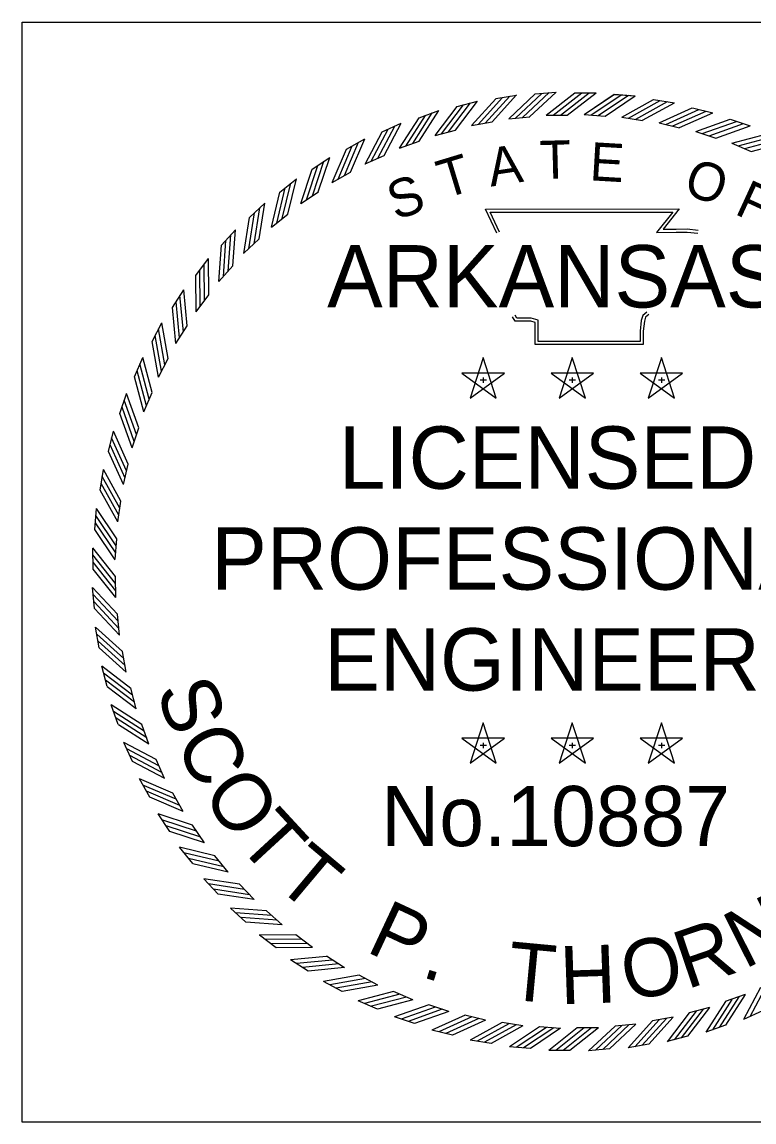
# Model space of a CAD drawing. Extents: x 0 to 1228740, y 0 to 152440.
# Drawn here: x 34.774 to 36.607, y 17.436 to 20.192 of the extents above; entities that cross this region are included whole.
import ezdxf

# ---------------------------------------------------------------- set-up
doc = ezdxf.new("R2010")
doc.units = 0
doc.layers.add('R_Sheet Text', color=7, linetype='Continuous')

msp = doc.modelspace()

# ---------------------------------------------------------------- linework, layer by layer
at = {"layer": 'R_Sheet Text'}
for p, q in [((36.0588, 20.0118), (36.1112, 20.0166)), ((36.1585, 20.0147), (36.2111, 20.0147)), ((35.8631, 19.9801), (35.914, 19.9935)), ((35.9603, 20), (36.0121, 20.0091)), ((36.257, 20.0107), (36.3095, 20.0069)), ((36.2571, 20.0108), (36.3096, 20.0069)), ((36.3554, 19.998), (36.4074, 19.9898)), ((35.7679, 19.9523), (35.8175, 19.9699)), ((36.0866, 19.9587), (36.1394, 19.9587)), ((36.1812, 19.9602), (36.2339, 19.9563)), ((36.1813, 19.9602), (36.2339, 19.9563)), ((36.4524, 19.9771), (36.5035, 19.9647)), ((35.6753, 19.9167), (35.7233, 19.9383)), ((35.8993, 19.9324), (35.9513, 19.9415)), ((35.9924, 19.9494), (36.045, 19.9542)), ((36.2757, 19.9538), (36.3279, 19.9456)), ((36.3694, 19.9397), (36.4206, 19.9272)), ((36.5473, 19.9483), (36.5972, 19.9317)), ((35.8079, 19.9077), (35.8589, 19.9211)), ((36.4615, 19.9179), (36.5115, 19.9012)), ((35.586, 19.8736), (35.632, 19.8991)), ((35.7189, 19.8756), (35.7686, 19.8932)), ((36.5515, 19.8886), (36.6, 19.8678)), ((35.5005, 19.8233), (35.5443, 19.8525)), ((35.6328, 19.8362), (35.6809, 19.8578)), ((35.4195, 19.766), (35.4607, 19.7987)), ((35.5503, 19.7899), (35.5964, 19.8154)), ((35.4718, 19.7368), (35.5157, 19.7661)), ((35.3435, 19.7023), (35.3819, 19.7383)), ((35.398, 19.6775), (35.4394, 19.7103)), ((35.273, 19.6325), (35.3083, 19.6716)), ((35.3294, 19.6124), (35.3679, 19.6484)), ((35.2085, 19.5572), (35.2404, 19.599)), ((35.2664, 19.5417), (35.3017, 19.5809)), ((35.1504, 19.4767), (35.1788, 19.5211)), ((35.2094, 19.4661), (35.2414, 19.508)), ((35.0992, 19.3918), (35.1238, 19.4383)), ((35.1589, 19.3861), (35.1873, 19.4305)), ((35.0552, 19.3029), (35.0759, 19.3513)), ((35.9285, 19.3507), (35.8956, 19.2497)), ((35.9613, 19.2498), (35.9286, 19.3509)), ((36.1517, 19.3507), (36.1188, 19.2497)), ((36.1845, 19.2498), (36.1518, 19.3509)), ((36.3749, 19.3507), (36.342, 19.2497)), ((36.4077, 19.2498), (36.375, 19.3509)), ((35.1151, 19.3021), (35.1398, 19.3487)), ((35.9816, 19.3122), (35.8753, 19.3123)), ((35.8754, 19.3122), (35.9613, 19.2497)), ((35.8957, 19.2498), (35.9817, 19.3122)), ((35.9286, 19.3009), (35.9286, 19.2876)), ((36.2048, 19.3122), (36.0986, 19.3123)), ((36.0986, 19.3122), (36.1845, 19.2497)), ((36.1189, 19.2498), (36.2049, 19.3122)), ((36.1518, 19.3009), (36.1518, 19.2876)), ((36.428, 19.3122), (36.3218, 19.3123)), ((36.3218, 19.3122), (36.4077, 19.2497)), ((36.3421, 19.2498), (36.4281, 19.3122)), ((36.375, 19.3009), (36.375, 19.2876)), ((35.9209, 19.2952), (35.9367, 19.2952)), ((36.1441, 19.2952), (36.1599, 19.2952)), ((36.3674, 19.2952), (36.3831, 19.2952)), ((35.0187, 19.2107), (35.0353, 19.2606)), ((35.0784, 19.2149), (35.0992, 19.2633)), ((34.9899, 19.1157), (35.0023, 19.1669)), ((35.0491, 19.1248), (35.0658, 19.1749)), ((35.0273, 19.0327), (35.0398, 19.084)), ((34.969, 19.0188), (34.9772, 19.0708)), ((34.9563, 18.9204), (34.9601, 18.9729)), ((35.0132, 18.9391), (35.0214, 18.9912)), ((35.0068, 18.8447), (35.0107, 18.8973)), ((34.9517, 18.8213), (34.9512, 18.8739)), ((35.0083, 18.75), (35.0078, 18.8028)), ((34.9552, 18.7222), (34.9504, 18.7746)), ((35.0176, 18.6558), (35.0128, 18.7083)), ((34.967, 18.6237), (34.9579, 18.6755)), ((35.0346, 18.5627), (35.0255, 18.6146)), ((34.9869, 18.5265), (34.9735, 18.5774)), ((35.0593, 18.4713), (35.0459, 18.5223)), ((35.0147, 18.4313), (34.9971, 18.4809)), ((35.0914, 18.3823), (35.0738, 18.432)), ((35.9285, 18.4355), (35.8956, 18.3345)), ((35.9613, 18.3346), (35.9286, 18.4357)), ((36.1517, 18.4355), (36.1188, 18.3345)), ((36.1845, 18.3346), (36.1518, 18.4357)), ((36.3749, 18.4355), (36.342, 18.3345)), ((36.4077, 18.3346), (36.375, 18.4357)), ((35.0503, 18.3387), (35.0287, 18.3867)), ((35.9816, 18.397), (35.8753, 18.3971)), ((35.8754, 18.397), (35.9613, 18.3345)), ((35.8957, 18.3346), (35.9817, 18.397)), ((36.2048, 18.397), (36.0986, 18.3971)), ((36.0986, 18.397), (36.1845, 18.3345)), ((36.1189, 18.3346), (36.2049, 18.397)), ((36.428, 18.397), (36.3218, 18.3971)), ((36.3218, 18.397), (36.4077, 18.3345)), ((36.3421, 18.3346), (36.4281, 18.397)), ((35.9209, 18.38), (35.9367, 18.38)), ((35.9286, 18.3857), (35.9286, 18.3724)), ((36.1441, 18.38), (36.1599, 18.38)), ((36.1518, 18.3857), (36.1518, 18.3724)), ((36.3674, 18.38), (36.3831, 18.38)), ((36.375, 18.3857), (36.375, 18.3724)), ((35.1308, 18.2962), (35.1092, 18.3443)), ((35.0934, 18.2494), (35.0679, 18.2954)), ((35.1771, 18.2136), (35.1516, 18.2598)), ((35.1437, 18.1639), (35.1145, 18.2077)), ((35.2302, 18.1352), (35.2009, 18.1791)), ((35.201, 18.0829), (35.1683, 18.1241)), ((35.2895, 18.0614), (35.2567, 18.1027)), ((35.2647, 18.0068), (35.2287, 18.0452)), ((35.3546, 17.9928), (35.3186, 18.0312)), ((35.3345, 17.9364), (35.2954, 17.9716)), ((35.4253, 17.9297), (35.3862, 17.9651)), ((35.4098, 17.8719), (35.368, 17.9038)), ((35.5009, 17.8728), (35.459, 17.9048)), ((35.4903, 17.8138), (35.4459, 17.8422)), ((35.5809, 17.8222), (35.5365, 17.8507)), ((35.5752, 17.7626), (35.5287, 17.7872)), ((35.6649, 17.7785), (35.6183, 17.8032)), ((35.7522, 17.7418), (35.7037, 17.7626)), ((36.5847, 17.7548), (36.535, 17.7372)), ((35.6641, 17.7186), (35.6157, 17.7393)), ((35.8422, 17.7125), (35.7921, 17.7291)), ((35.7563, 17.682), (35.7064, 17.6987)), ((35.9343, 17.6907), (35.883, 17.7032)), ((36.4043, 17.698), (36.3524, 17.6888)), ((36.4957, 17.7227), (36.4447, 17.7093)), ((36.6283, 17.7137), (36.5803, 17.6921)), ((36.0279, 17.6766), (35.9758, 17.6848)), ((36.1223, 17.6702), (36.0697, 17.6741)), ((36.217, 17.6717), (36.1642, 17.6712)), ((36.3112, 17.681), (36.2587, 17.6761)), ((36.5357, 17.6781), (36.4861, 17.6605)), ((35.8513, 17.6533), (35.8001, 17.6657)), ((36.4405, 17.6503), (36.3896, 17.6369)), ((35.9482, 17.6324), (35.8963, 17.6406)), ((36.0466, 17.6196), (35.9941, 17.6235)), ((36.1457, 17.615), (36.0931, 17.6145)), ((36.2448, 17.6186), (36.1924, 17.6138)), ((36.3433, 17.6304), (36.2915, 17.6213))]:
    msp.add_line(p, q, dxfattribs=at)
msp.add_lwpolyline([(34.7735, 20.192), (37.53, 20.192), (37.53, 17.4355), (34.7735, 17.4355)], close=True, dxfattribs=at)
for points in [[(36.0093, 19.9508), (36.0756, 20.0131)], [(36.0274, 19.9528), (36.0938, 20.0152)], [(36.0449, 19.9543), (36.1113, 20.0166)], [(36.0866, 19.9586), (36.1584, 20.0146)], [(36.1035, 19.9585), (36.1753, 20.0145)], [(36.1218, 19.9589), (36.1936, 20.0149)], [(36.1393, 19.9587), (36.2111, 20.0147)], [(35.8419, 19.9168), (35.8971, 19.9893)], [(35.8589, 19.9211), (35.9141, 19.9936)], [(35.8993, 19.9323), (35.9602, 19.9999)], [(35.916, 19.9351), (35.977, 20.0027)], [(35.9339, 19.9387), (35.9949, 20.0063)], [(35.9512, 19.9416), (36.0122, 20.0092)], [(35.9924, 19.9494), (36.0587, 20.0117)], [(36.1812, 19.9601), (36.257, 20.0108)], [(36.1812, 19.9601), (36.2569, 20.0107)], [(36.1981, 19.9587), (36.2739, 20.0094)], [(36.1981, 19.9587), (36.2738, 20.0093)], [(36.2163, 19.9578), (36.2922, 20.0084)], [(36.2164, 19.9578), (36.2921, 20.0084)], [(36.2338, 19.9563), (36.3096, 20.007)], [(36.2338, 19.9563), (36.3096, 20.0069)], [(36.2757, 19.9538), (36.3553, 19.9979)], [(36.2924, 19.951), (36.372, 19.9951)], [(36.3105, 19.9486), (36.3901, 19.9927)], [(36.3278, 19.9457), (36.4074, 19.9898)], [(35.7349, 19.881), (35.7839, 19.9577)], [(35.752, 19.8875), (35.801, 19.9642)], [(35.7685, 19.8932), (35.8176, 19.9699)], [(35.8079, 19.9076), (35.8631, 19.9801)], [(35.8243, 19.9118), (35.8795, 19.9842)], [(36.3693, 19.9397), (36.4523, 19.9771)], [(36.3857, 19.9355), (36.4687, 19.9729)], [(36.4036, 19.9316), (36.4866, 19.969)], [(36.4205, 19.9273), (36.5036, 19.9647)], [(35.6648, 19.8508), (35.7073, 19.9313)], [(35.6808, 19.8578), (35.7233, 19.9384)], [(35.7188, 19.8755), (35.7679, 19.9522)], [(36.4614, 19.9179), (36.5472, 19.9483)], [(36.4774, 19.9124), (36.5632, 19.9428)], [(36.4949, 19.907), (36.5807, 19.9374)], [(36.5115, 19.9013), (36.5973, 19.9317)], [(35.6328, 19.8361), (35.6753, 19.9166)], [(35.6483, 19.8429), (35.6908, 19.9235)], [(36.5514, 19.8885), (36.6394, 19.9118)], [(36.5669, 19.8817), (36.6549, 19.905)], [(35.5651, 19.7978), (35.6008, 19.8816)], [(35.5809, 19.807), (35.6166, 19.8908)], [(35.5963, 19.8154), (35.6321, 19.8991)], [(36.5839, 19.8749), (36.6719, 19.8982)], [(36.5999, 19.8679), (36.688, 19.8911)], [(35.5156, 19.7661), (35.5443, 19.8525)], [(35.5502, 19.7898), (35.5859, 19.8735)], [(35.4718, 19.7368), (35.5005, 19.8232)], [(35.486, 19.746), (35.5147, 19.8325)], [(35.501, 19.7565), (35.5296, 19.8429)], [(35.4393, 19.7103), (35.4607, 19.7988)], [(35.398, 19.6775), (35.4195, 19.766)], [(35.4114, 19.6879), (35.4328, 19.7764)], [(35.4254, 19.6995), (35.4469, 19.788)], [(35.3678, 19.6484), (35.3819, 19.7384)], [(35.3418, 19.6237), (35.3559, 19.7137)], [(35.3549, 19.6365), (35.369, 19.7265)], [(35.9624, 19.6625), (35.9343, 19.7232), (36.4197, 19.7235), (36.3791, 19.6726), (36.4121, 19.673), (36.4396, 19.6734), (36.4672, 19.6704)], [(35.9694, 19.6657), (35.9464, 19.7156), (36.4037, 19.7158), (36.363, 19.6647), (36.4122, 19.6653), (36.4393, 19.6657), (36.4663, 19.6627)], [(35.3294, 19.6123), (35.3435, 19.7022)], [(35.2898, 19.5679), (35.2964, 19.6587)], [(35.3017, 19.5808), (35.3083, 19.6716)], [(35.2664, 19.5416), (35.273, 19.6325)], [(35.2778, 19.5541), (35.2844, 19.6449)], [(35.2413, 19.508), (35.2404, 19.5991)], [(35.2306, 19.4942), (35.2296, 19.5852)], [(35.2094, 19.466), (35.2085, 19.5571)], [(35.2198, 19.4794), (35.2189, 19.5705)], [(35.1872, 19.4305), (35.1788, 19.5211)], [(35.1681, 19.4002), (35.1597, 19.4908)], [(35.1777, 19.4158), (35.1692, 19.5064)], [(35.1589, 19.386), (35.1504, 19.4767)], [(36.3383, 19.4651), (36.3282, 19.4568), (36.3246, 19.4438), (36.3217, 19.4176), (36.3217, 19.3913), (36.0662, 19.3913), (36.0662, 19.4289), (36.0662, 19.4447), (36.0487, 19.45), (36.0131, 19.45), (36.0086, 19.457)], [(35.1397, 19.3487), (35.1238, 19.4384)], [(36.3432, 19.4591), (36.3349, 19.4524), (36.3322, 19.4423), (36.3294, 19.4172), (36.3294, 19.3836), (36.0585, 19.3836), (36.0585, 19.4289), (36.0585, 19.439), (36.0475, 19.4423), (36.009, 19.4423), (36.0021, 19.4528)], [(35.1232, 19.3169), (35.1073, 19.4066)], [(35.1314, 19.3333), (35.1155, 19.4229)], [(35.1151, 19.302), (35.0992, 19.3917)], [(35.0991, 19.2633), (35.0759, 19.3513)], [(35.0921, 19.2472), (35.0688, 19.3353)], [(35.0785, 19.2148), (35.0552, 19.3028)], [(35.0853, 19.2303), (35.062, 19.3183)], [(35.06, 19.1583), (35.0296, 19.2441)], [(35.0657, 19.1748), (35.0353, 19.2607)], [(35.0546, 19.1408), (35.0242, 19.2266)], [(35.0491, 19.1248), (35.0187, 19.2106)], [(35.0397, 19.0839), (35.0023, 19.1669)], [(35.0315, 19.0491), (34.9941, 19.1321)], [(35.0354, 19.0669), (34.998, 19.1499)], [(35.0273, 19.0327), (34.9899, 19.1157)], [(35.0184, 18.9739), (34.9743, 19.0535)], [(35.0213, 18.9912), (34.9772, 19.0708)], [(35.016, 18.9558), (34.9719, 19.0354)], [(35.0132, 18.9391), (34.9691, 19.0187)], [(35.0107, 18.8972), (34.9601, 18.9729)], [(35.0083, 18.8615), (34.9577, 18.9372)], [(35.0092, 18.8797), (34.9586, 18.9555)], [(35.0069, 18.8446), (34.9563, 18.9203)], [(35.0078, 18.8027), (34.9511, 18.874)], [(35.0078, 18.7852), (34.9511, 18.8565)], [(35.0084, 18.7669), (34.9517, 18.8382)], [(35.0084, 18.75), (34.9517, 18.8212)], [(35.0127, 18.7083), (34.9504, 18.7746)], [(35.0142, 18.6908), (34.9518, 18.7572)], [(35.0163, 18.6726), (34.9539, 18.739)], [(35.0177, 18.6558), (34.9553, 18.7221)], [(35.0254, 18.6146), (34.9578, 18.6756)], [(35.0283, 18.5973), (34.9607, 18.6583)], [(35.0319, 18.5793), (34.9643, 18.6403)], [(35.0347, 18.5626), (34.9671, 18.6236)], [(35.0459, 18.5222), (34.9734, 18.5774)], [(35.0502, 18.5052), (34.9777, 18.5604)], [(35.0552, 18.4877), (34.9828, 18.5429)], [(35.0594, 18.4713), (34.9869, 18.5264)], [(35.0738, 18.4319), (34.9971, 18.4809)], [(35.0795, 18.4153), (35.0028, 18.4644)], [(35.086, 18.3982), (35.0093, 18.4473)], [(35.0915, 18.3822), (35.0148, 18.4312)], [(35.1092, 18.3442), (35.0286, 18.3867)], [(35.1162, 18.3281), (35.0357, 18.3707)], [(35.1241, 18.3116), (35.0436, 18.3542)], [(35.1309, 18.2961), (35.0504, 18.3387)], [(35.1516, 18.2597), (35.0679, 18.2954)], [(35.16, 18.2443), (35.0762, 18.28)], [(35.1692, 18.2285), (35.0854, 18.2642)], [(35.1772, 18.2136), (35.0935, 18.2493)], [(35.2009, 18.179), (35.1145, 18.2077)], [(35.2105, 18.1643), (35.1241, 18.193)], [(35.221, 18.1493), (35.1345, 18.178)], [(35.2302, 18.1352), (35.1438, 18.1639)], [(35.2567, 18.1027), (35.1682, 18.1241)], [(35.2675, 18.0888), (35.179, 18.1103)], [(35.2791, 18.0748), (35.1906, 18.0962)], [(35.2895, 18.0614), (35.201, 18.0828)], [(35.3186, 18.0312), (35.2286, 18.0452)], [(35.3305, 18.0183), (35.2405, 18.0323)], [(35.3433, 18.0052), (35.2533, 18.0193)], [(35.3547, 17.9928), (35.2648, 18.0068)], [(35.3862, 17.965), (35.2954, 17.9716)], [(35.3991, 17.9532), (35.3083, 17.9598)], [(35.4129, 17.9412), (35.3221, 17.9478)], [(35.4254, 17.9297), (35.3345, 17.9363)], [(35.459, 17.9047), (35.3679, 17.9038)], [(35.4728, 17.894), (35.3818, 17.893)], [(35.4876, 17.8832), (35.3966, 17.8823)], [(35.501, 17.8728), (35.4099, 17.8719)], [(35.5365, 17.8506), (35.4459, 17.8422)], [(35.5512, 17.841), (35.4606, 17.8326)], [(35.5668, 17.8315), (35.4762, 17.8231)], [(35.581, 17.8223), (35.4904, 17.8138)], [(35.6183, 17.8031), (35.5286, 17.7872)], [(35.6337, 17.7948), (35.5441, 17.7789)], [(35.6501, 17.7866), (35.5604, 17.7707)], [(36.6389, 17.7796), (36.5963, 17.6991)], [(35.665, 17.7785), (35.5753, 17.7626)], [(35.7037, 17.7625), (35.6157, 17.7393)], [(35.7198, 17.7555), (35.6317, 17.7322)], [(36.5848, 17.7549), (36.5358, 17.6781)], [(36.6228, 17.7725), (36.5803, 17.692)], [(35.7367, 17.7486), (35.6487, 17.7254)], [(35.7522, 17.7418), (35.6642, 17.7186)], [(35.7922, 17.7291), (35.7063, 17.6987)], [(36.5351, 17.7372), (36.4861, 17.6605)], [(36.5517, 17.7429), (36.5026, 17.6662)], [(36.5688, 17.7494), (36.5197, 17.6726)], [(35.8087, 17.7234), (35.7229, 17.693)], [(35.8262, 17.718), (35.7404, 17.6876)], [(35.8422, 17.7125), (35.7564, 17.6821)], [(35.8831, 17.7031), (35.8001, 17.6657)], [(35.9001, 17.6988), (35.8171, 17.6614)], [(36.4044, 17.6981), (36.3434, 17.6305)], [(36.4448, 17.7092), (36.3896, 17.6368)], [(36.4618, 17.7135), (36.4066, 17.6411)], [(36.4793, 17.7186), (36.4241, 17.6462)], [(36.4957, 17.7227), (36.4406, 17.6503)], [(35.9179, 17.6949), (35.8349, 17.6574)], [(35.9343, 17.6907), (35.8513, 17.6533)], [(35.9758, 17.6847), (35.8962, 17.6406)], [(35.9931, 17.6818), (35.9135, 17.6377)], [(36.0112, 17.6794), (35.9316, 17.6352)], [(36.0279, 17.6766), (35.9483, 17.6324)], [(36.0698, 17.674), (35.9941, 17.6235)], [(36.0873, 17.6726), (36.0115, 17.622)], [(36.1055, 17.6717), (36.0298, 17.6211)], [(36.1224, 17.6703), (36.0467, 17.6197)], [(36.1643, 17.6712), (36.093, 17.6145)], [(36.1818, 17.6712), (36.1106, 17.6145)], [(36.2001, 17.6717), (36.1288, 17.6151)], [(36.217, 17.6717), (36.1458, 17.6151)], [(36.2587, 17.6761), (36.1924, 17.6138)], [(36.2762, 17.6775), (36.2098, 17.6152)], [(36.2944, 17.6796), (36.228, 17.6173)], [(36.3112, 17.681), (36.2449, 17.6187)], [(36.3524, 17.6888), (36.2914, 17.6212)], [(36.3697, 17.6917), (36.3087, 17.6241)], [(36.3877, 17.6953), (36.3267, 17.6277)]]:
    msp.add_lwpolyline(points, dxfattribs=at)

# ---------------------------------------------------------------- texts
for s, height, rotation, p in [('A', 0.0957, 8.6788, (35.9476, 19.7793)), ('T', 0.0959, 1.4789, (36.071, 19.7982)), ('T', 0.0957, 1.4789, (36.0712, 19.7984)), ('E', 0.0957, 356.672, (36.1937, 19.7955)), ('T', 0.0957, 16.9015, (35.8314, 19.749)), ('O', 0.0957, 341.2218, (36.4262, 19.7626)), ('S', 0.0957, 19.7726, (35.7096, 19.6943)), ('F', 0.0957, 335.3628, (36.5552, 19.7122)), ('S', 0.1454, 289.7007, (35.1081, 18.5182)), ('C', 0.1454, 296.9967, (35.1548, 18.3876)), ('O', 0.1454, 304.6575, (35.2214, 18.2581)), ('T', 0.1454, 312.6831, (35.3089, 18.1333)), ('T', 0.1454, 319.9791, (35.4029, 18.0313)), ('N', 0.1454, 26.7376, (36.5826, 17.8173)), ('P', 0.1454, 334.9359, (35.6318, 17.8639)), ('R', 0.1454, 18.712, (36.4385, 17.7674)), ('O', 0.1454, 10.6864, (36.2888, 17.7382)), ('T', 0.1454, 354.6351, (35.9846, 17.7434)), ('H', 0.1454, 1.9312, (36.1227, 17.7304)), ('.', 0.1454, 342.9615, (35.7704, 17.8002))]:
    msp.add_text(s, height=height, rotation=rotation, dxfattribs=at).set_placement(p)
for s, height, p in [('ARKANSAS', 0.15625, (35.5376, 19.4766)), ('LICENSED', 0.15625, (35.5674, 19.0224)), ('PROFESSIONAL', 0.156246, (35.2474, 18.7695)), ('ENGINEER', 0.15625, (35.5302, 18.5165)), ('No.10887', 0.15067, (35.673, 18.1269))]:
    msp.add_text(s, height=height, dxfattribs=at).set_placement(p)

doc.saveas('drawing.dxf')
